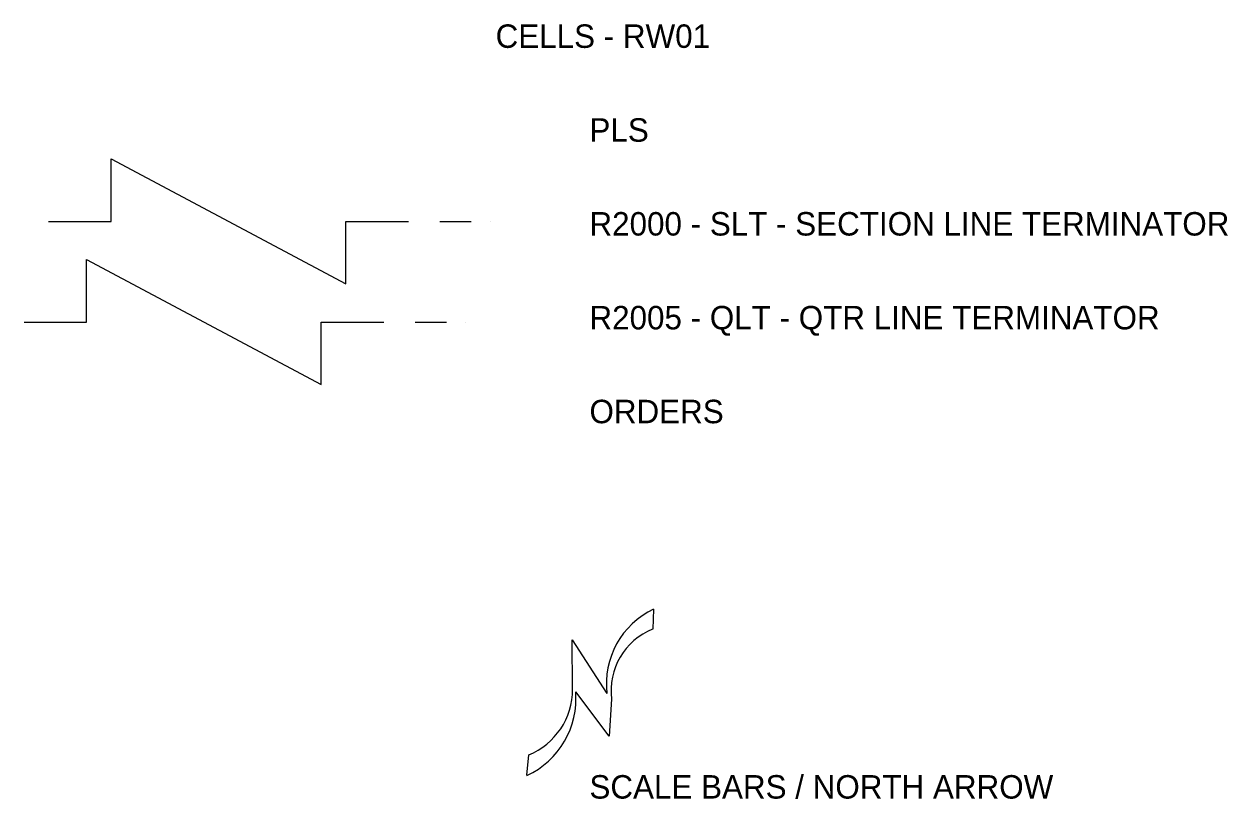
# Model space of a CAD drawing. Extents: x 2147716 to 2176321, y 2125040 to 2131750.
# Drawn here: x 2170284.9 to 2170669.7, y 2129460.1 to 2129707.8 of the extents above; entities that cross this region are included whole.
import ezdxf

# ---------------------------------------------------------------- set-up
doc = ezdxf.new("R2010")
doc.units = 0
for name, color, linetype in [('Default', 7, 'Continuous'), ('MAP DATA', 7, 'Continuous'), ('PLS INP', 7, 'Continuous')]:
    doc.layers.add(name, color=color, linetype=linetype)

msp = doc.modelspace()

# ---------------------------------------------------------------- linework, layer by layer
at = {"layer": 'MAP DATA'}
for p, q in [((2170486.13, 2129520.78), (2170485.83, 2129514.38)), ((2170445.63, 2129467.68), (2170446.23, 2129474.18))]:
    msp.add_line(p, q, dxfattribs=at)
for points in [[(2170460.23, 2129495.18), (2170460.13, 2129510.98), (2170471.23, 2129493.78)], [(2170472.63, 2129491.98), (2170471.93, 2129480.18), (2170461.23, 2129494.38)]]:
    msp.add_lwpolyline(points, dxfattribs=at)
for centre, radius, start, end in [((2170497.33, 2129496.98), 26.3, 115.1894, 186.9899), ((2170493.73, 2129494.68), 21.23, 111.8515, 187.258), ((2170434.23, 2129492.18), 27.09, 294.9528, 4.6583), ((2170437.53, 2129495.18), 22.73, 292.5035, 0)]:
    msp.add_arc(centre, radius, start, end, dxfattribs=at)
at = {"layer": 'PLS INP'}
for p, q in [((2170312.78, 2129644.76), (2170312.78, 2129664.76)), ((2170312.78, 2129664.76), (2170387.78, 2129624.76)), ((2170292.78, 2129644.76), (2170312.78, 2129644.76)), ((2170387.78, 2129624.76), (2170387.78, 2129644.76)), ((2170387.78, 2129644.76), (2170407.78, 2129644.76)), ((2170417.78, 2129644.76), (2170427.78, 2129644.76)), ((2170433.98, 2129644.76), (2170433.98, 2129644.76)), ((2170304.93, 2129612.58), (2170304.93, 2129632.58)), ((2170304.93, 2129632.58), (2170379.93, 2129592.58)), ((2170284.93, 2129612.58), (2170304.93, 2129612.58)), ((2170379.93, 2129592.58), (2170379.93, 2129612.58)), ((2170379.93, 2129612.58), (2170399.93, 2129612.58)), ((2170409.93, 2129612.58), (2170419.93, 2129612.58)), ((2170426.13, 2129612.58), (2170426.13, 2129612.58))]:
    msp.add_line(p, q, dxfattribs=at)

# ---------------------------------------------------------------- texts
at = {"layer": 'Default'}
for s, p in [('CELLS - RW01', (2170435.63, 2129700.23)), ('PLS', (2170465.63, 2129670.23)), ('R2000 - SLT - SECTION LINE TERMINATOR', (2170465.63, 2129640.23)), ('R2005 - QLT - QTR LINE TERMINATOR', (2170465.63, 2129610.23)), ('ORDERS', (2170465.63, 2129580.23)), ('SCALE BARS / NORTH ARROW', (2170465.63, 2129460.23))]:
    msp.add_text(s, height=7.5, dxfattribs=at).set_placement(p)

doc.saveas('drawing.dxf')
